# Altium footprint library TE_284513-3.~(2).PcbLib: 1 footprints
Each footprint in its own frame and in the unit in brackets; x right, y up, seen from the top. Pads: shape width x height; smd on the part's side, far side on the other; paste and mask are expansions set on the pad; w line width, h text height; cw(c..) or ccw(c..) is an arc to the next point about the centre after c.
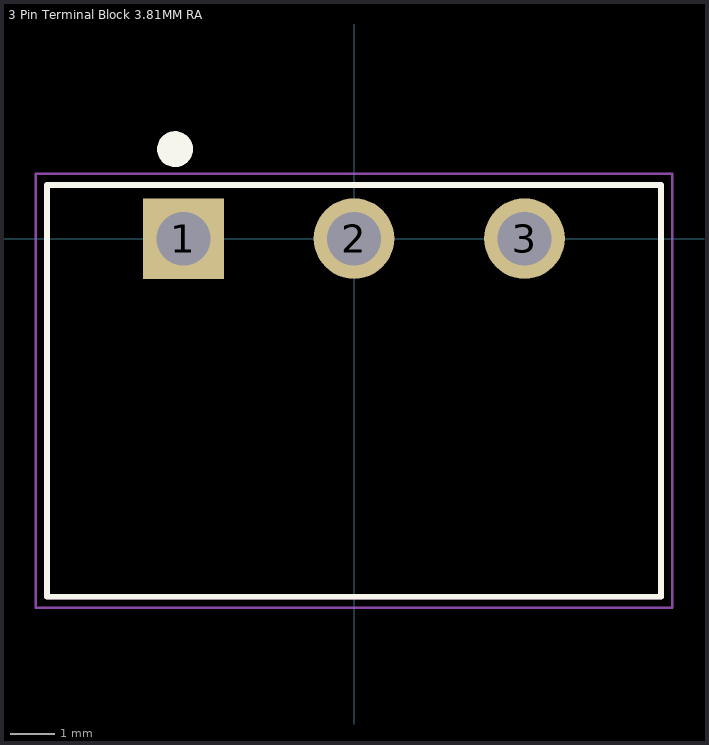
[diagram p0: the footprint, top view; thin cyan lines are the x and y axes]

## 3 Pin Terminal Block 3.81MM RA [mm] "3 Pin Terminal Block HDR 3.81MM THT RA 284513-3"
pads (3):
  rect 1.8x1.8 hole 1.2: 1(-3.81,0)
  round 1.8 hole 1.2: 2(0,0) 3(3.81,0)
Top Overlay:
  circle w0.4: c-4,2 r0.2
  lines w0.127: -6.86,-8 6.86,-8 6.86,1.2 -6.86,1.2 -6.86,-8
Mechanical 13:
  lines w0.127: -6.86,-8 -6.86,1.2 6.86,1.2 6.86,-8 -6.86,-8
Mechanical 15:
  lines w0.05: -7.11,-8.25 -7.11,1.45 7.11,1.45 7.11,-8.25 -7.11,-8.25
3D body "step_temp.STEP": height 4.3, standoff -6.4, extent -6.86,-8.001 6.86,1.199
